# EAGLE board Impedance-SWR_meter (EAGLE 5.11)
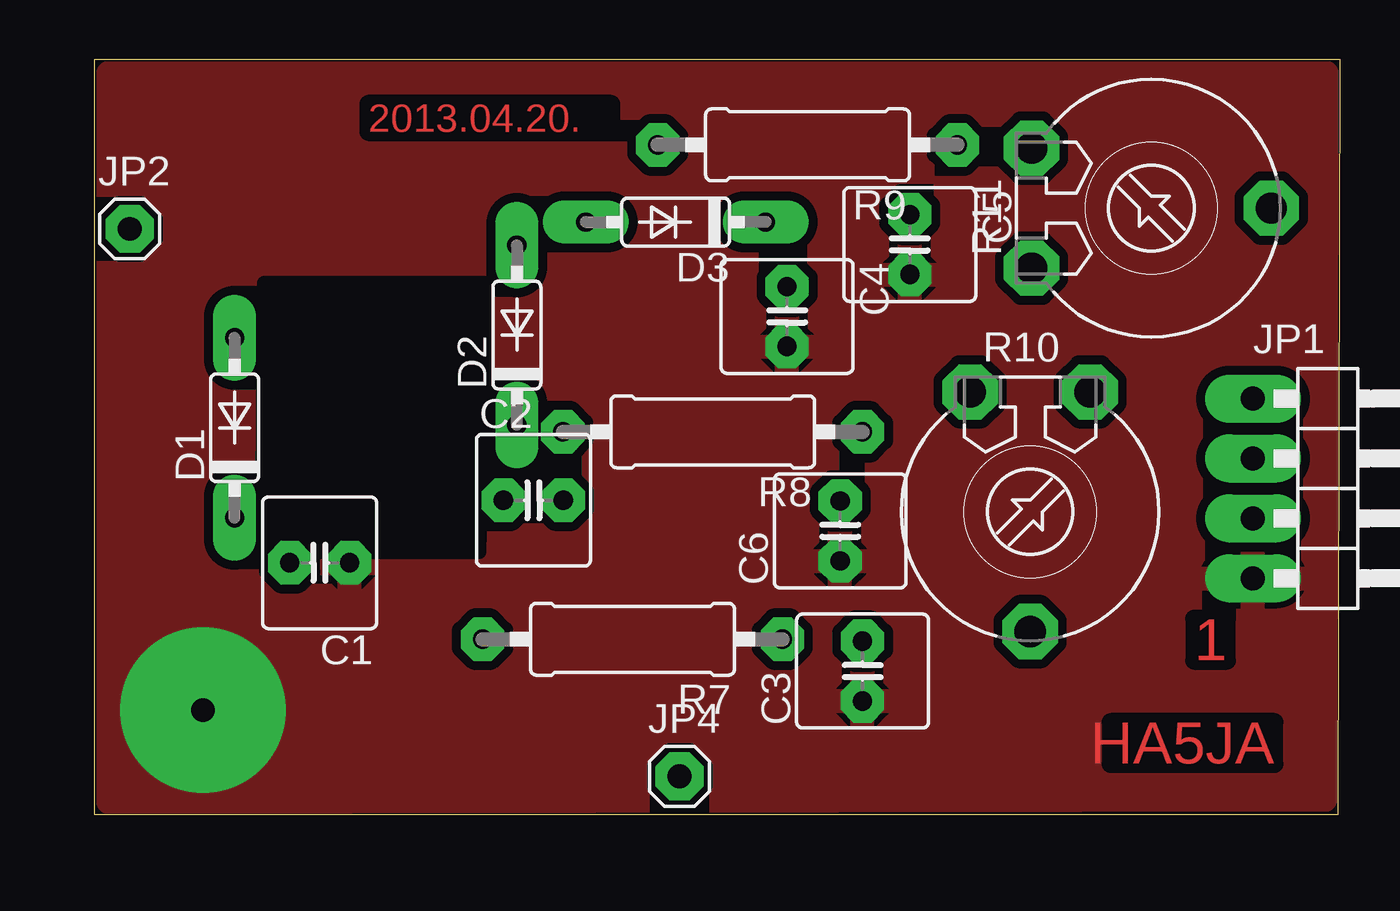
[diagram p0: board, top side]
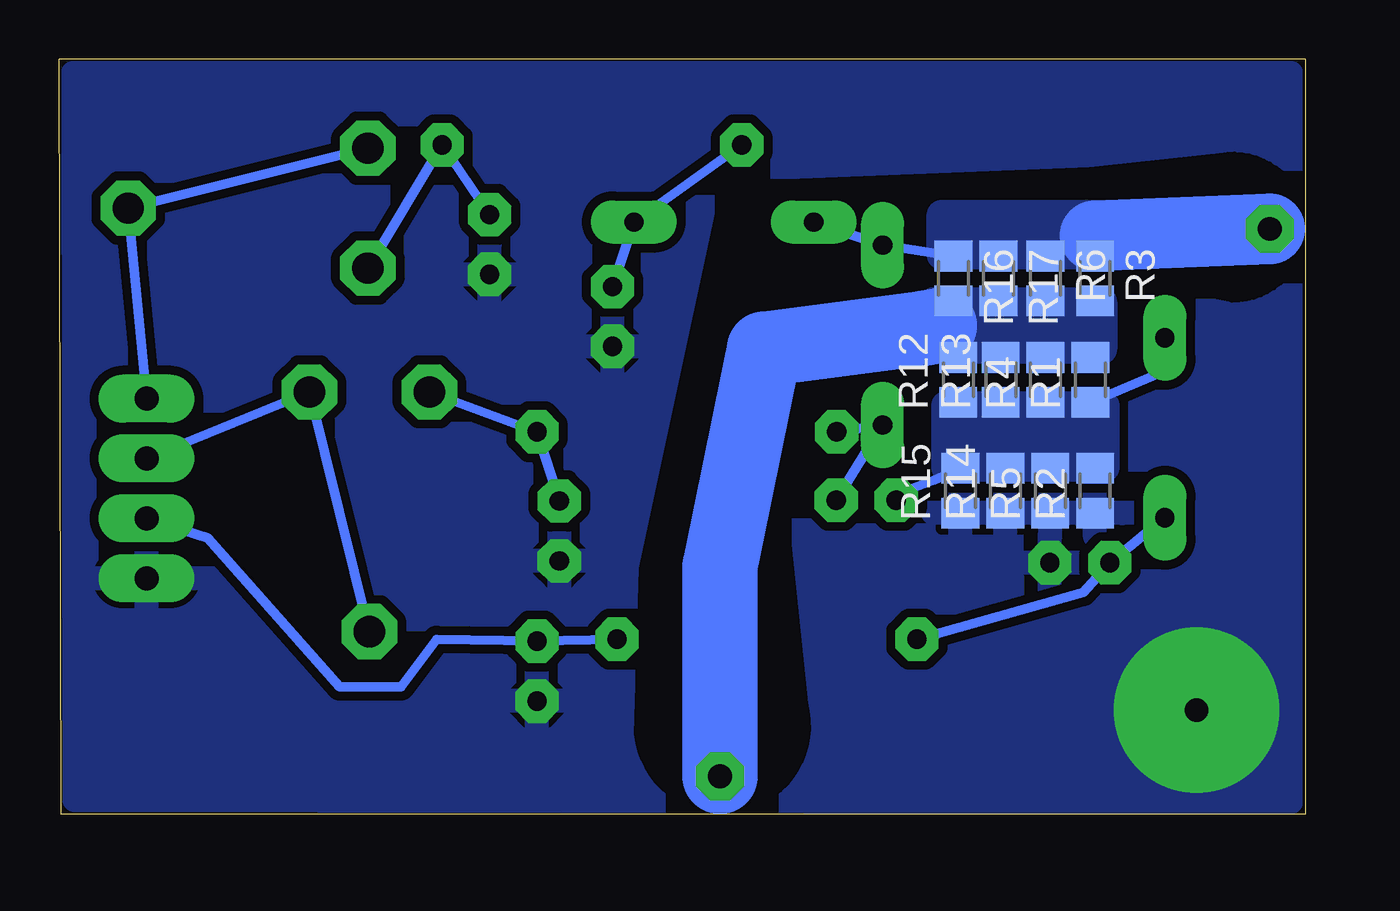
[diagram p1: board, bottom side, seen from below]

Size 52.8 x 32 mm. Coordinates in mm from the lower left corner, seen from the top.
Outline: 52.7,0 52.8,32 0,32 0,0 52.7,0
Copper layers (1*16): Top 0.035mm / dielectric 1.5mm / Bottom 0.035mm
Design rules "default *": minimum track width 10mil, minimum drill 24mil, track to track 15mil, track to pad 15mil, pad to pad 8mil, via to via 8mil, smd to smd 8mil, copper to edge 0mil, drill to drill 8mil, minimum pad ring 20mil, minimum via ring 8mil, stop-mask expansion 4mil, vias tented up to drill 0mil, thermal gap 10mil
tRestrict: area 7.1,11.1 to 16.6,22.5
bRestrict: area 0,0.1 to 28.3,27.9

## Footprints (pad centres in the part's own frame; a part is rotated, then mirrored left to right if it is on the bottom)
C025-060X050 = drill 0.813 octagon: 1 -1.27,0; 2 1.27,0
DO35-7 = drill 0.813 long: A 3.81,0; C -3.81,0
1X04/90 = drill 1.016 long: 1 -3.81,-3.81; 2 -1.27,-3.81; 3 1.27,-3.81; 4 3.81,-3.81
1X01 = drill 1.016 octagon: 1 0,0
M0805 = smd 1.3 x 1.6: 1 -0.95,0; 2 0.95,0
0309/12 = drill 0.813 octagon: 1 -6.35,0; 2 6.35,0
LI10 = drill 1.321 octagon: A -2.54,-5.08; E 2.54,-5.08; S 0,5.08

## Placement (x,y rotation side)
C1  470p  [C025-060X050]  9.54,10.65 180 top
C2  470p  [C025-060X050]  18.6,13.3 0 top
C3  100n  [C025-060X050]  32.55,6.06 90 top
C4  470p  [C025-060X050]  29.35,21.09 270 top
C5  100n  [C025-060X050]  34.55,24.14 270 top
C6  100n  [C025-060X050]  31.6,12 90 top
D1  1N4148DO35-7  [DO35-7]  5.94,16.37 90 top
D2  1N4148DO35-7  [DO35-7]  17.9,20.3 90 top
D3  1N4148DO35-7  [DO35-7]  24.63,25.09 180 top
JP1  To meter  [1X04/90]  52.9,13.8 270 top
JP2  To ant  [1X01]  1.5,24.8 0 top
JP4  RF in  [1X01]  24.8,1.6 0 top
R1  100  [M0805]  9.1,18.4 90 bottom
R2  100  [M0805]  8.9,13.7 90 bottom
R3  100  [M0805]  8.9,22.7 270 bottom
R4  100  [M0805]  11,18.4 90 bottom
R5  100  [M0805]  10.8,13.7 90 bottom
R6  100  [M0805]  11,22.7 270 bottom
R7  15k  [0309/12]  22.8,7.41 180 top
R8  10k  [0309/12]  26.2,16.2 180 top
R9  27k  [0309/12]  30.22,28.36 180 top
R10  10k  [LI10]  39.65,12.81 180 top
R11  10k  [LI10]  44.79,25.68 270 top
R12  100  [M0805]  14.7,18.4 90 bottom
R13  100  [M0805]  12.9,18.4 90 bottom
R14  100  [M0805]  12.7,13.7 90 bottom
R15  100  [M0805]  14.6,13.7 90 bottom
R16  100  [M0805]  14.9,22.7 270 bottom
R17  100  [M0805]  13,22.7 270 bottom

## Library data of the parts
C1-C6 R1-R9 R12-R17 = rcl
D1-D3 = diode
JP1 JP2 JP4 = pinhead
R10 R11 = pot

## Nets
GND: C1.1 C3.1 C4.2 C5.2 C6.1 JP1.4 R2.1 R5.1 R14.1 R15.1
N$1: C2.1 D1.A R1.1 R2.2 R4.1 R5.2 R12.1 R13.1 R14.2 R15.2
N$2: JP4.1 R1.2 R3.2 R4.2 R6.2 R12.2 R13.2 R16.2 R17.2
N$3: C1.2 D1.C R7.2
N$4: D2.A D3.A JP2.1 R3.1 R6.1 R16.1 R17.1
N$5: C3.2 JP1.3 R7.1
N$6: JP1.2 R10.A R10.S
N$7: C2.2 D2.C R8.2
N$8: C6.2 R8.1 R10.E
N$10: C4.1 D3.C R9.2
N$11: JP1.1 R11.A R11.S
N$15: C5.1 R9.1 R11.E

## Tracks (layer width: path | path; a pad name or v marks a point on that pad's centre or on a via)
GND  (via drill 1 pad 7)
  other vias: 4.6,4.4
  pour Bottom (rank 2): 0.6,31.4 52.2,31.4 52.15,0.6 0.6,0.5
  pour Top: 0.6,31.4 52.2,31.4 52.15,0.6 0.6,0.5
N$1
  Bottom 0.406: R15.2 15.7,14.15 16.73,13.77 C2.1 | R1.1 5.9,18.8 D1.A
  pour Bottom (no thermals): 8.5,14.7 15.2,14.7 15.2,17.3 8.5,17.3
N$2
  Bottom 0.406: R13.2 12.9,19.45 | 16.1,20.6 R12.2
  Bottom 3.2: 15.5,20.7 16.1,20.6 22.9,19.7 24.8,10.5 JP4.1
  pour Bottom (no thermals): 8.6,19.7 15.7,19.7 15.7,21.7 8.6,21.7
N$3
  Bottom 0.406: D1.C C1.2 9.4,9.4 R7.2
N$4
  Bottom 0.406: R16.1 D2.A D3.A | 8.9,24.5 R3.1
  Bottom 3: JP2.1 8.9,24.5
  pour Bottom (no thermals): 8.5,23.7 15.4,23.7 15.4,25.4 8.5,25.4
N$5
  Bottom 0.406: R7.1 C3.2 36.8,7.4 38.3,5.4 40.9,5.4 46.5,11.7 JP1.3
N$6
  Bottom 0.406: R10.S R10.A JP1.2
N$7
  Bottom 0.406: C2.2 D2.C R8.2
N$8
  Bottom 0.406: C6.2 R8.1 R10.E
N$10
  Bottom 0.406: R9.2 D3.C C4.1
N$11
  Bottom 0.406: R11.A R11.S JP1.1
N$15
  Bottom 0.406: C5.1 R9.1 R11.E

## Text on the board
Top: 2013.04.20. | 1 | HA5JA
